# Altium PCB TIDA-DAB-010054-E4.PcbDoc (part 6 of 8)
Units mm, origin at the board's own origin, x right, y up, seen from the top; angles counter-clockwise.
Board outline 300 x 180 mm, 4 copper layers (Top Layer, Inner Layer1, Inner Layer2, Bottom Layer), stack 1.605 mm thick; 873 components, 388 nets, 2405 pads, 1542 vias.
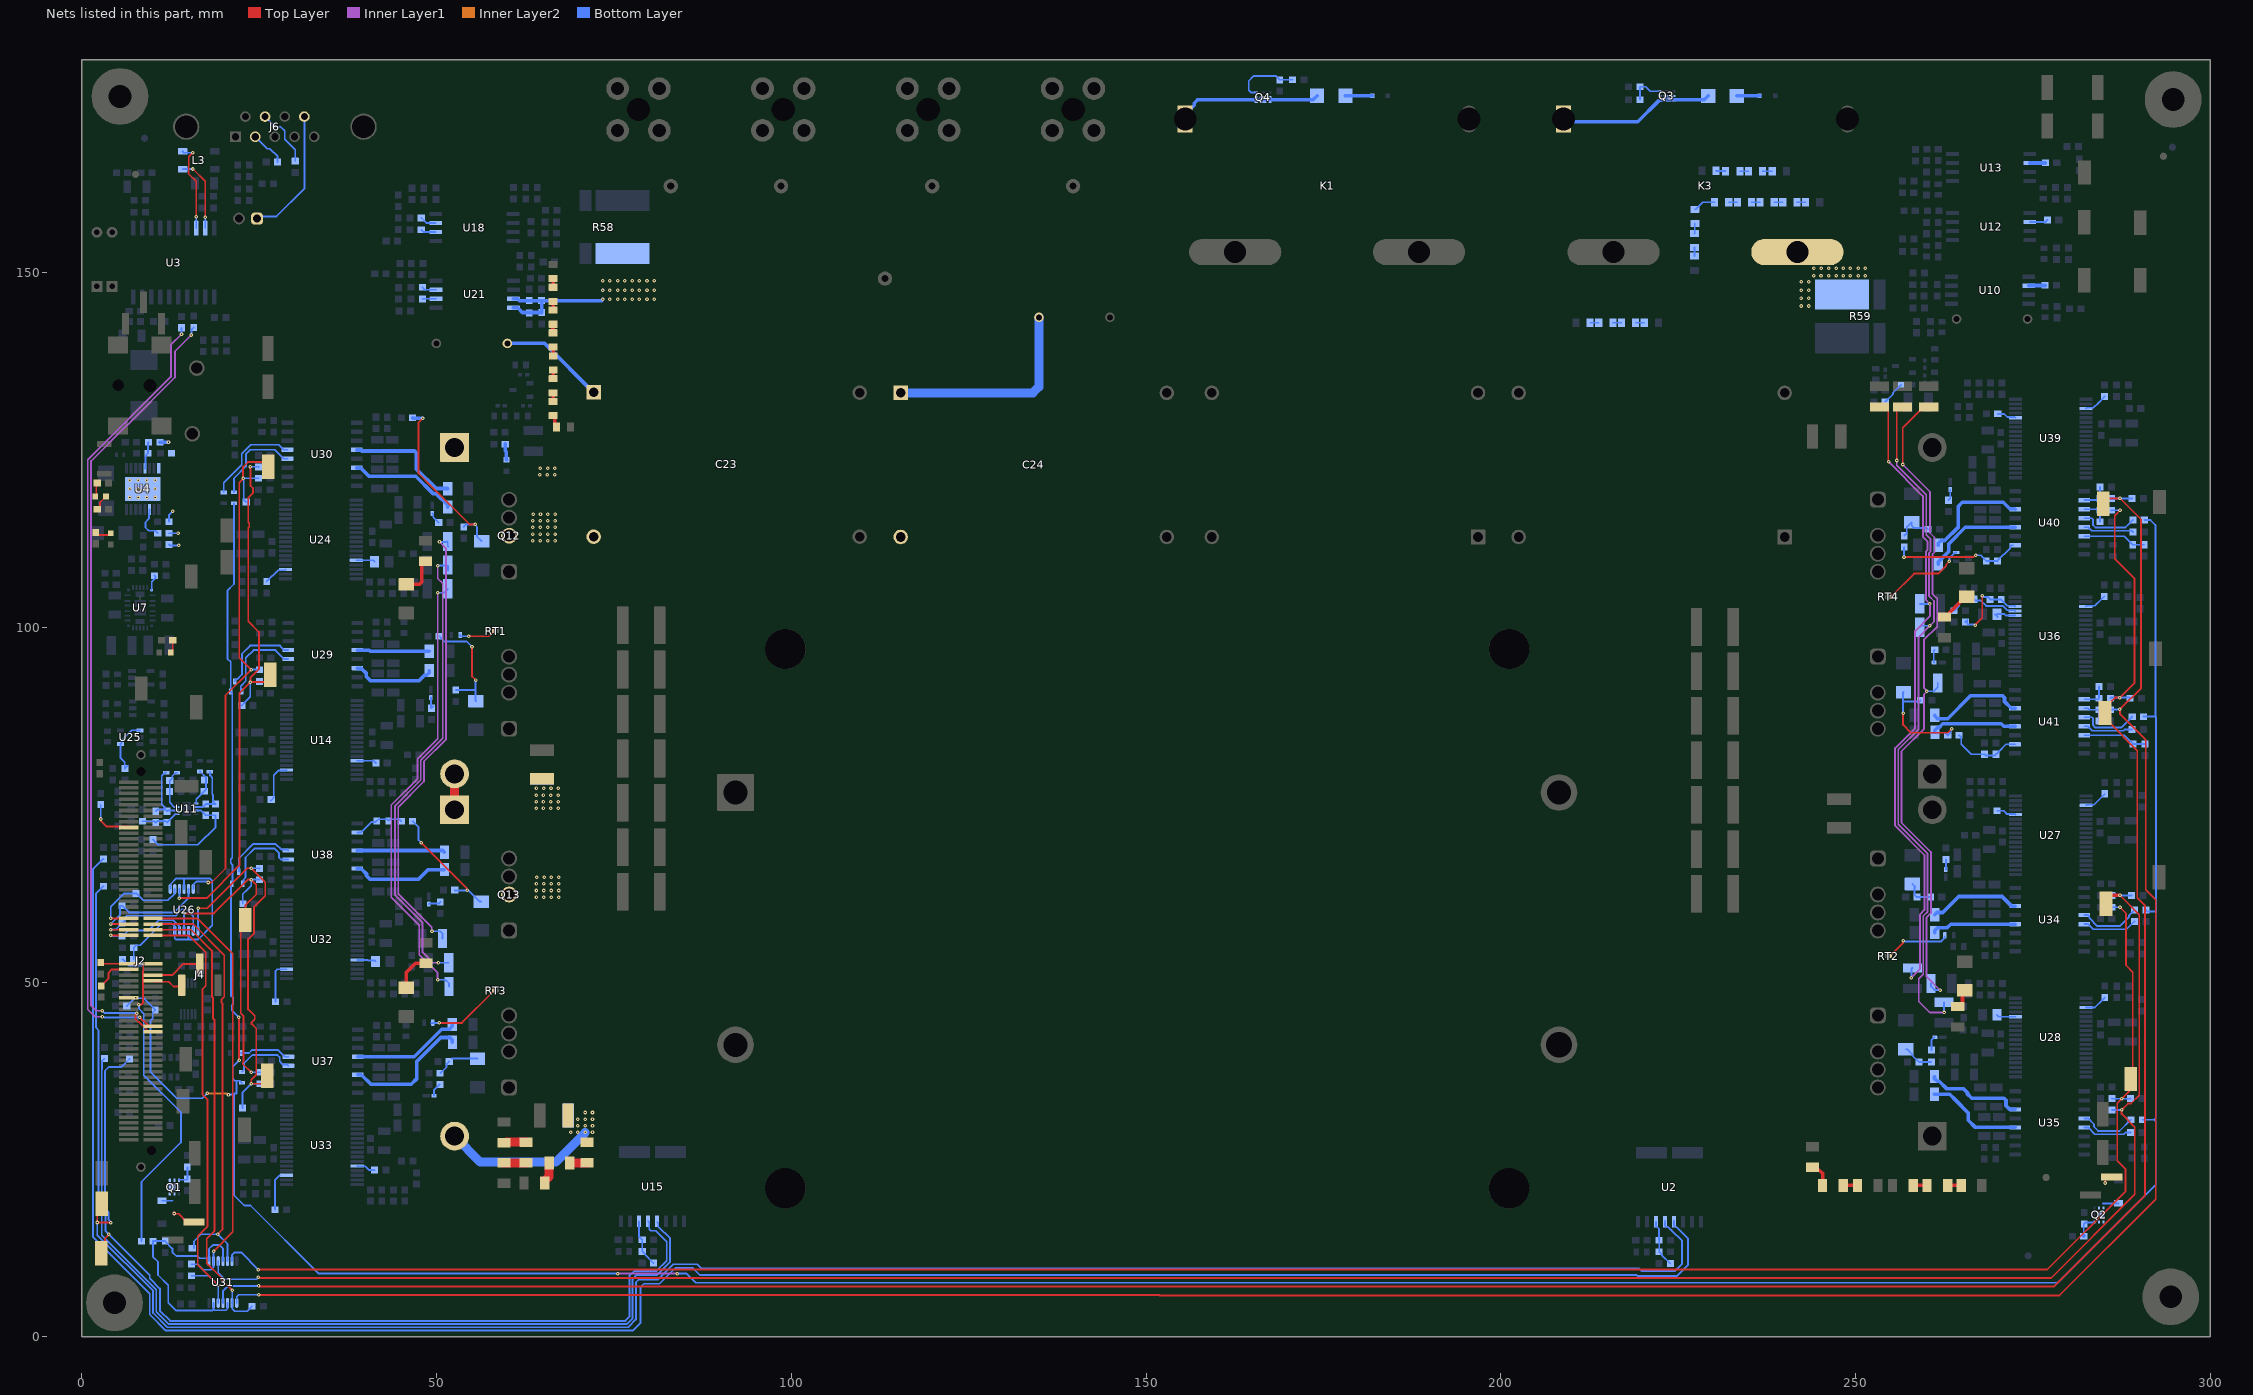
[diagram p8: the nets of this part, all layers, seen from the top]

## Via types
v1: diameter 0.5, hole 0.2, Top Layer to Bottom Layer, tented both sides, 1530 vias
v2: diameter 0.5, hole 0.2, Top Layer to Bottom Layer, 12 vias

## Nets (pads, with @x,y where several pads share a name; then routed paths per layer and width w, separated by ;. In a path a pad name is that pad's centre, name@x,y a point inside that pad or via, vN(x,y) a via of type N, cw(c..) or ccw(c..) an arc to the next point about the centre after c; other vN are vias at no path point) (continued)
NetC283_1: C283.1 R346.1 R350.2 U36.34 | length 12
  Top Layer w0.254: v1(266.849,100.307) 266.849,100.359 267.847,101.358 267.847,104.433 v1(267.818,104.462)
  Bottom Layer w0.254: R346.1@265.467,100.755 265.724,101.012 265.724,100.523 265.84,100.407 266.682,100.407 266.782,100.307 v1(266.849,100.307) ; v1(267.818,104.462) 267.914,104.462 268.105,104.271 268.599,104.271 268.947,103.923 R350.2@268.947,103.898 C283.1@270.522,103.898 270.522,103.873 271.363,103.033 272.381,103.033 U36.34@272.476,102.938
NetC284_1: C284.1 R347.1 R351.2 U36.33 | length 10.3
  Bottom Layer w0.254: R347.1@263.867,102.34 263.892,102.34 264.588,103.037 264.588,103.313 264.782,103.507 264.782,103.602 265.327,104.147 266.53,104.147 266.903,103.774 267.629,103.774 268.39,103.013 270.71,103.013 271.339,102.383 272.381,102.383 U36.33@272.476,102.288
NetC293_1: C293.1 R352.2 U40.10 | length 3.9
  Bottom Layer w0.254: U40.10@282.225,117.911 284.218,117.911 R352.2@284.436,118.129 C293.1@284.436,119.763
NetC299_1: C299.1 R353.2 U41.10 | length 3.8
  Bottom Layer w0.254: U41.10@282.205,89.851 284.14,89.851 R353.2@284.289,89.999 C299.1@284.289,91.65
NetC302_1: C302.1 R322.1 R326.2 U38.2 | length 7.3
  Bottom Layer w0.254: U38.2@38.866,71.087 39.391,71.087 40.871,72.567 41.471,72.567 41.844,72.94 43.086,72.94 R326.2@43.304,72.723 43.521,72.94 44.759,72.94 R322.1@45.052,72.648
NetC303_1: C303.1 R354.2 U40.11 | length 3.9
  Bottom Layer w0.254: U40.11@282.225,116.641 284.244,116.641 R354.2@284.416,116.469 284.436,116.449 C303.1@284.436,114.861
NetC304_1: C304.1 R355.2 U41.11 | length 3.8
  Bottom Layer w0.254: U41.11@282.205,88.581 282.73,88.581 282.929,88.382 R355.2@284.289,88.382 C304.1@284.289,86.793
NetC305_1: C305.1 R375.2 U40.14 | length 8.9
  Bottom Layer w0.254: U40.14@282.225,112.831 287.857,112.831 289.036,111.653 C305.1@289.036,111.628 R375.2@290.625,111.628
NetC308_1: C308.1 R372.1 R377.2 U40.2 | length 18.4
  Top Layer w0.254: v1(256.816,109.852) 256.846,109.882 266.559,109.882 266.832,110.154 v1(266.898,110.154)
  Bottom Layer w0.254: v1(256.816,109.852) 256.816,111.253 R372.1@256.862,111.299 ; v1(266.898,110.154) 267.608,110.154 268.057,109.706 268.057,109.681 R377.2@268.405,109.333 C308.1@269.976,109.333 269.976,109.358 271.777,111.159 271.777,111.388 271.95,111.561 U40.2@272.2,111.561
NetC309_1: C309.1 R376.2 U41.14 | length 9.1
  Bottom Layer w0.254: U41.14@282.205,84.771 287.861,84.771 288.724,83.908 288.749,83.908 289.097,83.56 C309.1@289.097,83.535 R376.2@290.786,83.535
NetC312_1: C312.1 R374.1 R378.2 U41.2 | length 10.3
  Bottom Layer w0.254: R374.1@264.586,84.766 264.869,84.483 264.869,83.516 266.281,82.104 R378.2@268.164,82.104 268.32,81.948 269.636,81.948 C312.1@269.791,82.104 269.791,82.129 270.139,82.477 270.164,82.477 271.189,83.501 U41.2@272.455,83.501
NetC315_1: C315.1 R135.1 R138.1 U11.2 | length 8.9
  Bottom Layer w0.254: R135.1@10.457,74.075 10.687,74.305 11.708,74.305 11.708,74.668 11.698,74.678 11.673,74.678 11.313,75.039 11.313,79.088 11.744,79.519 R138.1@11.944,79.519 ; C315.1@11.826,74.305 C315.1@12.056,74.075 12.14,74.159 U11.2@13.455,74.159
NetC315_2: C315.2 R135.2 R139.1 U11.1 | length 5.8
  Bottom Layer w0.254: R139.1@8.601,72.66 10.272,72.66 R135.2@10.457,72.475 10.684,72.702 11.829,72.702 C315.2@12.056,72.475 12.056,72.5 12.404,72.848 12.423,72.848 U11.1@13.234,73.659 ; U11.1@13.234,73.659 U11.1@13.455,73.659 U11.1@13.234,73.659
NetC316_1: C316.1 R142.1 R143.2 U11.3 | length 6
  Bottom Layer w0.254: U11.3@13.455,74.659 13.453,74.661 13.084,74.661 12.43,75.315 12.43,78.392 R143.2@12.427,78.395 12.442,78.395 12.79,78.743 12.79,79.038 13.255,79.502 R142.1@13.455,79.502
NetC317_1: C317.1 R153.1 R156.1 U11.6 | length 7.8
  Bottom Layer w0.254: U11.6@16.155,74.659 16.954,74.659 17.028,74.732 17.145,74.732 17.493,75.08 C317.1@17.493,75.105 17.493,75.097 R153.1@18.886,75.097 18.538,75.445 18.538,76.33 18.427,76.441 18.427,78.81 18.12,79.117 18.12,79.517 18.088,79.548 R156.1@18.088,79.64
NetC317_2: C317.2 R153.2 R157.1 U11.7 | length 14.9
  Bottom Layer w0.254: R157.1@10.06,70.077 10.085,70.077 10.822,69.34 16.406,69.34 18.886,71.82 R153.2@18.886,73.497 17.493,73.497 17.493,73.53 16.866,74.157 16.157,74.157 U11.7@16.155,74.159
NetC318_1: C318.1 R159.1 R160.2 U11.5 | length 5.4
  Bottom Layer w0.254: U11.5@16.155,75.159 16.155,75.781 17.265,76.89 R160.2@17.29,76.89 17.52,77.12 17.52,78.841 R159.1@16.69,79.67
NetC333_1: C333.1 R37.2 R40.1 U2.8 | length 6.7
  Bottom Layer w0.254: U2.8@221.855,16.205 221.855,15.68 222.288,15.247 C333.1@222.288,13.614 222.314,13.589 R40.1@222.314,11.989 222.339,11.989 222.687,11.641 222.687,11.514 223.863,10.338 R37.2@223.888,10.338
NetC334_1: C334.1 R45.2 R46.1 U15.8 | length 6.8
  Bottom Layer w0.254: U15.8@78.562,16.309 78.562,14.123 79.007,13.678 R46.1@79.007,12.04 79.032,12.04 79.38,11.692 79.38,11.616 80.582,10.414 R45.2@80.607,10.414
NetD1_2: D1.2 D2.2 | length 3.8
  Bottom Layer w0.508: D2.2@178.118,174.904 D1.2@181.884,174.904
NetD3_2: D3.2 D4.2 | length 3.2
  Bottom Layer w0.508: D4.2@233.24,174.88 D3.2@236.46,174.88
NetD6_1: D6.1 R68.1 | length 2
  Top Layer w0.254: D6.1@1.948,118.425 2.085,118.562 2.085,120.185 R68.1@2.216,120.316
NetD6_2: D6.2 R70.2 | length 2.3
  Top Layer w0.254: R70.2@2.216,116.631 2.241,116.631 2.589,116.979 2.589,117.576 3.302,118.289 3.312,118.289 D6.2@3.448,118.425
NetD8_1: D8.1 R76.2 | length 2.4
  Top Layer w0.254: R76.2@2,113.37 2,113.345 2.358,112.987 3.865,112.987 D8.1@4.134,113.256
NetD10_1: D10.1 R81.2 | length 1.9
  Top Layer w0.254: D10.1@12.558,96.435 12.831,96.708 12.831,96.83 12.858,96.857 R81.2@12.858,98.161
NetD11_1: D11.1 R13.1 | length 3.4
  Bottom Layer w0.254: R13.1@254.166,131.773 254.191,131.773 255.27,132.852 255.27,133.054 D11.1@256.4,134.184
NetD12_1: D12.1 R14.1 | length 2.3
  Bottom Layer w0.508: R14.1@59.691,125.832 59.691,124.904 59.84,124.756 59.84,123.646 D12.1@59.891,123.594
NetD13_2: D13.2 J1.2 Q1.1 Q1.2 Q1.5 Q1.6 Q1.8 | length 4.8
  Top Layer w0.254: v1(13.083,17.387) 13.13,17.34 13.69,17.34 14.85,16.18 J1.2@15.85,16.18
  Top Layer w0.508: v1@13.057,17.361 v1(13.083,17.387)
  Bottom Layer w0.254: D13.2@11.333,19.196 12.804,19.196
NetD14_2: D14.2 R208.1 R217.2 | length 15.9
  Top Layer w0.254: v1(55.022,97.225) 55.022,93.073 v1(55.532,92.563)
  Bottom Layer w0.254: R217.2@50.413,98.725 50.438,98.725 50.786,98.377 50.786,98.352 51.144,97.993 54.254,97.993 v1(55.022,97.225) ; R208.1@52.729,91.15 55.532,91.15 ; v1(55.532,92.563) 55.532,91.15 ; D14.2@55.569,89.593 55.532,89.63 55.532,91.15
NetD15_2: D15.2 R154.1 R155.2 | length 25
  Top Layer w0.254: v1(48.099,129.474) 47.498,128.872 47.498,121.662 49.283,119.877 54.675,114.485 v1(55.468,114.485)
  Bottom Layer w0.254: R154.1@53.858,114.135 53.858,114.137 54.206,114.485 v1(55.468,114.485) 55.468,114.419 55.725,114.162 55.725,112.766 D15.2@56.381,112.11
  Bottom Layer w0.508: R155.2@46.661,129.512 46.7,129.474 v1(48.099,129.474)
NetD16_2: D16.2 J3.2 Q2.1 Q2.2 Q2.5 Q2.6 Q2.8 | length 3.8
  Top Layer w0.254: v1@285.155,21.657 v1(285.183,21.685) 285.183,22.182 285.556,22.555 J3.2@286.082,22.555
  Bottom Layer w0.254: 284.812,18.808 D16.2@287.032,18.808
NetD17_2: D17.2 R24.1 | length 1.7
  Bottom Layer w0.254: D17.2@49.443,116.062 49.566,115.939 49.566,115.492 50.311,114.747 R24.1@50.336,114.747
NetD18_2: D18.2 R267.1 R276.2 | length 4.1
  Bottom Layer w0.254: D18.2@257.991,63.825 258.399,63.418 258.29,63.309 258.29,62.323 258.638,61.975 R276.2@258.663,61.975 R267.1@260.54,61.975
NetD19_2: D19.2 R273.1 R278.2 | length 4.4
  Bottom Layer w0.254: D19.2@257.063,40.545 257.253,40.545 258.016,39.782 258.016,39.619 258.888,38.748 R278.2@258.913,38.748 R273.1@260.668,38.748
NetD20_2: D20.2 R25.1 | length 1.8
  Bottom Layer w0.254: D20.2@49.24,90.082 49.24,88.647 R25.1@49.301,88.586 ; R25.1@49.404,88.793 49.458,88.74 R25.1@49.578,88.86
NetD21_2: D21.2 R26.1 | length 1.4
  Bottom Layer w0.254: D21.2@262.716,65.874 R26.1@262.716,67.297
NetD22_2: D22.2 R317.1 R322.2 | length 17.3
  Top Layer w0.254: v1(47.889,69.628) 54.291,63.226 54.291,62.969 v1(54.338,62.921)
  Bottom Layer w0.254: R322.2@46.652,72.648 46.677,72.648 47.5,71.825 47.5,70.017 v1(47.889,69.628) ; R317.1@52.591,62.972 52.642,62.921 v1(54.338,62.921) 54.385,62.874 54.591,62.874 56.13,61.335 D22.2@56.32,61.335
NetD23_2: D23.2 R27.1 | length 2
  Bottom Layer w0.254: R27.1@260.704,40.415 260.704,41.868 261.053,42.217 D23.2@261.153,42.217
NetD24_2: D24.2 R6.2 | length 5.5
  Top Layer w0.508: D24.2@45.778,106.049 47.62,106.049 47.917,106.347 47.917,108.901 48.313,109.297 R6.2@48.467,109.297
NetD25_2: D25.2 R362.1 R372.2 | length 5.5
  Bottom Layer w0.254: R372.2@256.862,112.899 257.21,113.247 257.21,114.065 257.719,114.574 D25.2@257.917,114.773 257.917,114.318 258.255,113.98 R362.1@260.031,113.98 ; R362.1@260.031,113.98 R362.1@260.2,113.811 R362.1@260.031,113.98
NetD26_2: D26.2 R311.1 R320.2 | length 5.8
  Bottom Layer w0.254: R311.1@50.539,37.155 50.564,37.155 51.443,38.034 51.443,38.455 51.791,38.803 R320.2@51.816,38.803 ; R320.2@52.196,39.213 D26.2@55.798,39.213
NetD27_2: D27.2 R369.1 R374.2 | length 16.4
  Top Layer w0.254: v1(256.687,87.852) 256.687,86.231 257.774,85.144 263.009,85.144 v1(263.553,85.688)
  Bottom Layer w0.254: v1(256.687,87.852) 256.687,89.541 ; D27.2@256.745,90.855 256.687,90.797 256.687,89.541 ; R369.1@259.181,89.708 259.013,89.541 256.687,89.541 ; R374.2@262.638,85.114 R374.2@262.986,84.766 263.011,84.766 263.359,85.114 263.359,85.398 263.553,85.591 v1(263.553,85.688)
NetD28_2: D28.2 R7.2 | length 2.8
  Top Layer w0.508: R7.2@264.386,46.57 264.661,46.57 265.057,46.966 265.057,48.526 D28.2@265.367,48.835
NetD29_2: D29.2 R20.2 | length 5.5
  Top Layer w0.508: D29.2@45.773,49.197 45.773,51.348 47.071,52.646 R20.2@48.534,52.646
NetD30_2: D30.2 R21.2 | length 4.4
  Top Layer w0.508: R21.2@262.512,101.432 262.787,101.432 263.183,101.828 263.183,102.012 265.447,104.275 D30.2@265.637,104.275
NetD31_2: D31.2 R31.1 | length 1.7
  Bottom Layer w0.254: D31.2@48.957,60.988 49.029,61.059 50.35,61.059 R31.1@50.564,61.273
NetD32_2: D32.2 R32.1 | length 1.9
  Bottom Layer w0.254: D32.2@49.684,33.993 49.684,34.808 50.459,35.583 R32.1@50.484,35.583
NetD33_2: D33.2 R34.1 | length 1.9
  Bottom Layer w0.254: D33.2@261.058,95.031 261,95.09 261,96.697 R34.1@261.145,96.842
NetD34_2: D34.2 R35.1 | length 1.6
  Bottom Layer w0.254: R35.1@263.078,117.897 263.332,118.151 D34.2@263.332,119.418
NetJ2_17: J2.17 R3.2 | length 6.6
  Top Layer w0.254: v1(2.714,72.982) 2.761,72.934 2.761,72.668 3.144,72.285 3.527,71.902 6.546,71.902 J2.17@6.669,71.779
  Bottom Layer w0.254: v1(2.714,72.982) R3.2@2.714,74.996
NetJ2_57: J2.57 R10.2 | length 4
  Top Layer w0.254: R10.2@2.718,52.759 2.898,52.579 J2.57@6.669,52.579
NetJ2_59: J2.59 R19.2 | length 5.3
  Top Layer w0.254: R19.2@2.766,49.469 2.766,49.494 3.114,49.842 3.139,49.842 3.81,50.513 3.81,51.308 4.281,51.779 J2.59@6.669,51.779
NetJ2_80: J2.80 R38.1 | length 111.7
  Top Layer w0.254: v1(8.183,45.014) 8.652,44.545 8.786,44.545 9.429,43.902 9.946,43.902 J2.80@10.069,43.779
  Inner Layer1 w0.254: v1(2.949,45.104) 1.917,45.104 0.889,46.132 0.889,123.622 6.134,128.867 6.176,128.867 12.59,135.281 12.59,139.823 v1(14.085,141.317)
  Bottom Layer w0.254: v1(2.949,45.104) 2.996,45.057 3.17,45.057 3.213,45.014 v1(8.183,45.014) ; v1(14.085,141.317) R38.1@14.085,142.211
NetJ2_82: J2.82 R41.1 | length 112.6
  Top Layer w0.254: v1(7.778,45.626) 7.778,45.559 7.603,45.384 7.603,44.773 7.955,44.422 8.043,44.422 9.363,43.102 9.946,43.102 J2.82@10.069,42.979
  Inner Layer1 w0.254: v1(2.924,45.952) 2.074,45.952 1.346,46.68 1.346,123.433 6.323,128.41 6.366,128.41 13.166,135.21 13.166,138.888 v1(15.459,141.181)
  Bottom Layer w0.254: v1(2.924,45.952) 3.251,45.626 v1(7.778,45.626) ; v1(15.459,141.181) 15.481,141.203 15.481,141.895 R41.1@15.826,142.24
NetJ6_2: J6.2 R56.2 | length 5.1
  Bottom Layer w0.254: J6.2@24.475,169.12 26.158,167.437 26.543,167.437 27.63,166.35 R56.2@27.63,165.547
NetJ6_7: J6.7 R53.2 | length 8.5
  Bottom Layer w0.254: J6.7@25.86,171.96 27.28,170.54 28.038,170.54 28.63,169.947 28.63,168.752 30.112,167.27 R53.2@30.112,165.677
NetJ6_9: J6.9 J10.1 | length 18.6
  Bottom Layer w0.254: J10.1@24.728,157.596 25.013,157.881 27.467,157.881 31.4,161.814 J6.9@31.4,171.96
NetK3_4: K3.4 R59.4
  other v1: 242.333,145.272 243.38,145.272 242.305,146.342 243.38,146.342 242.333,147.472 243.38,147.472 242.338,148.672 243.38,148.672 244.119,149.528 245.119,149.528 246.219,149.528 247.239,149.528 248.251,149.528 249.251,149.528 250.351,149.528 251.371,149.528 244.128,150.56 245.128,150.56 246.228,150.56 247.248,150.56 248.26,150.56 249.26,150.56 250.36,150.56 251.38,150.56
NetL3_1: L3.1 U3.19 | length 10.5
  Top Layer w0.254: v1(15.701,164.572) 17.435,162.839 v1(17.435,157.748)
  Bottom Layer w0.254: L3.1@14.245,164.55 14.267,164.572 v1(15.701,164.572) ; U3.19@17.435,156.24 v1(17.435,157.748)
NetL3_2: L3.2 U3.18 | length 12.8
  Top Layer w0.254: v1(15.673,166.867) 15.121,166.315 15.121,163.874 16.165,162.83 v1(16.165,157.852)
  Bottom Layer w0.254: L3.2@14.245,167.05 14.428,166.867 v1(15.673,166.867) ; U3.18@16.165,156.24 v1(16.165,157.852)
NetQ1_3: Q1.3 R1.2 R2.2 | length 2.9
  Bottom Layer w0.254: Q1.3@13.733,22.146 14.813,22.146 R2.2@14.913,22.245 R1.2@14.913,23.91
NetQ2_3: Q2.3 R4.2 R5.2 | length 3.4
  Bottom Layer w0.254: R4.2@282.14,14.2 282.14,15.845 282.425,16.129 283.622,16.129 283.645,16.152 Q2.3@283.645,16.204
  Bottom Layer w0.508: R4.2@282.14,14.2 R4.2@282.182,14.242
NetQ3_3: Q3.3 R48.2 R51.2 | length 4.8
  Bottom Layer w0.254: R51.2@219.6,174.32 R48.2@219.6,176.16 220.436,176.16 221.066,175.53 Q3.3@222.299,175.53
NetQ4_3: Q4.3 R39.2 R43.2 | length 9.2
  Bottom Layer w0.254: Q4.3@165.535,175.336 164.804,175.336 164.48,175.66 164.48,176.979 165.201,177.7 168.3,177.7 168.487,177.513 168.512,177.513 168.86,177.165 R43.2@168.86,177.14 R39.2@170.64,177.14
NetR8_1: R8.1 U24.32 | length 2.7
  Bottom Layer w0.254: U24.32@38.715,109.435 41.108,109.435 R8.1@41.303,109.24
NetR9_1: R9.1 U28.32 | length 2.7
  Bottom Layer w0.254: R9.1@269.909,45.372 270.161,45.12 U28.32@272.525,45.12
NetR11_1: R11.1 U32.32 | length 2.7
  Bottom Layer w0.254: U32.32@38.855,53.115 40.299,53.115 40.36,53.054 41.294,53.054 R11.1@41.448,52.9
NetR12_1: R12.1 U36.32 | length 3.1
  Bottom Layer w0.254: R12.1@269.649,101.807 R12.1@269.997,101.459 ; R12.1@269.932,101.807 269.984,101.859 270.965,101.859 271.17,101.654 272.459,101.654 U36.32@272.476,101.638
NetR16_2: R16.2 RT1.2 | length 5.2
  Top Layer w0.254: v1(54.544,98.725) 57.417,98.725 58.025,99.332 RT1.2@58.025,99.457
  Bottom Layer w0.254: R16.2@53.346,98.901 53.346,98.835 53.457,98.725 v1(54.544,98.725)
NetR17_2: R17.2 RT2.2 | length 9.2
  Top Layer w0.254: RT2.2@254.955,53.668 254.955,53.793 256.658,55.496 256.658,55.758 v1(256.705,55.805)
  Bottom Layer w0.254: v1(256.705,55.805) 256.785,55.725 262.054,55.725 262.568,56.239 R17.2@262.568,56.452
NetR18_2: R18.2 RT3.2 | length 10.7
  Top Layer w0.254: v1(50.425,44.246) 53.598,44.246 57.977,48.624 57.977,48.749 RT3.2@58.025,48.797
  Bottom Layer w0.254: 49.252,44.27 49.276,44.246 v1(50.425,44.246)
NetR29_2: R29.2 RT4.2 | length 12.3
  Top Layer w0.254: RT4.2@254.955,104.283 254.955,104.408 255.003,104.456 255.128,104.456 258.233,107.561 261.663,107.561 262.761,108.659 262.761,108.839 263.191,109.268 v1(263.191,109.301)
  Bottom Layer w0.254: v1(263.191,109.301) 263.238,109.348 263.238,109.809 263.954,110.525 R29.2@264.167,110.525
NetR61_1: R61.1 U21.7 | length 2
  Bottom Layer w0.254: R61.1@48.046,147.897 48.391,147.552 U21.7@49.953,147.552
NetR63_1: R63.1 U21.6 | length 1.9
  Bottom Layer w0.254: R63.1@48.024,146.255 48.051,146.282 U21.6@49.953,146.282
NetR64_1: R64.1 R95.1 | length 1.4
  Bottom Layer w0.254: R95.1@236.893,164.256 R64.1@238.251,164.256
NetR66_1: R66.1 R128.2 | length 3.1
  Top Layer w1.27: R66.1@59.525,27.37 59.8,27.37 59.86,27.43 R128.2@62.64,27.43
NetR73_1: R73.1 U4.11 | length 4.8
  Bottom Layer w0.254: U4.11@9.582,116.587 9.582,116.059 9.487,115.964 9.487,115.277 9.017,114.807 9.017,114.06 9.489,113.589 10.385,113.589 R73.1@10.733,113.24
NetR84_2: R84.2 U7.1 | length 2.3
  Bottom Layer w0.254: U7.1@9.883,105.243 9.883,106.402 10.408,106.927 10.408,107.143 R84.2@10.276,107.275
NetR85_2: R85.2 U29.12 | length 12.1
  Bottom Layer w0.254: R85.2@22.6,90.935 22.439,91.096 22.439,91.714 23.151,92.425 23.151,95.688 24.243,96.78 27.321,96.78 28.591,95.51 U29.12@29.116,95.51
NetR92_1: R92.1 U10.6 | length 2.3
  Bottom Layer w0.508: U10.6@274.39,148.135 274.413,148.158 276.677,148.158 R92.1@276.7,148.181
NetR95_2: R95.2 R97.1 | length 1.2
  Bottom Layer w0.254: R97.1@233.687,164.256 R95.2@234.893,164.256
NetR96_1: R96.1 R98.1 | length 1.2
  Bottom Layer w0.254: R96.1@227.3,152.298 R98.1@227.3,153.504
NetR97_2: R97.2 R100.2 | length 1.4
  Bottom Layer w0.254: R100.2@230.33,164.336 230.37,164.296 231.647,164.296 R97.2@231.687,164.256
NetR98_2: R98.2 R102.1 | length 1.4
  Bottom Layer w0.254: R98.2@227.3,155.504 227.34,155.544 R102.1@227.34,156.891
NetR101_1: R101.1 R103.2 | length 1.2
  Bottom Layer w0.254: R101.1@212.594,142.912 R103.2@213.799,142.912
NetR102_2: R102.2 R105.2 | length 3.2
  Bottom Layer w0.254: R102.2@227.34,158.891 227.465,158.891 228.462,159.888 R105.2@230.119,159.888
NetR103_1: R103.1 R107.1 | length 1.2
  Bottom Layer w0.254: R103.1@215.799,142.912 R107.1@217.004,142.912
NetR105_1: R105.1 R106.2 | length 1.2
  Bottom Layer w0.254: R105.1@232.119,159.888 R106.2@233.324,159.888
NetR106_1: R106.1 R108.2 | length 1.2
  Bottom Layer w0.254: R106.1@235.324,159.888 R108.2@236.529,159.888
NetR107_2: R107.2 R109.2 | length 1.2
  Bottom Layer w0.254: R107.2@219.004,142.912 R109.2@220.209,142.912
NetR108_1: R108.1 R110.1 | length 1.2
  Bottom Layer w0.254: R108.1@238.529,159.888 R110.1@239.734,159.888
NetR110_2: R110.2 R111.2 | length 1.2
  Bottom Layer w0.254: R110.2@241.734,159.888 R111.2@242.939,159.888
NetR112_2: R112.2 R124.2 | length 1.8
  Top Layer w0.508: R124.2@66.455,129.817 66.685,129.587 66.685,128.467 R112.2@66.915,128.237
NetR116_1: R116.1 U12.6 | length 2.6
  Bottom Layer w0.254: U12.6@274.543,157.097 276.717,157.097 R116.1@277.02,157.4
NetR117_1: R117.1 U13.6 | length 2.2
  Bottom Layer w0.508: U13.6@274.55,165.415 274.562,165.427 276.728,165.427 R117.1@276.74,165.44
NetR124_1: R124.1 R145.2 | length 1.2
  Top Layer w0.508: R124.1@66.455,131.817 R124.1@66.455,131.817 66.457,133.028 R145.2@66.458,133.03
NetR125_1: R125.1 TP16.1 U2.7 | length 277.8
  Top Layer w0.254: TP16.1@2.851,18.777 2.222,18.148 v1(2.222,16.12) 2.226,16.116 4.132,16.116 v1(4.136,16.112)
  Bottom Layer w0.254: v1(2.222,16.12) 2.222,14.332 10.079,6.475 10.079,3.364 12.097,1.346 77.011,1.346 78.124,2.458 78.124,7.669 78.553,8.098 81.239,8.098 83.376,10.235 86.767,10.235 87.352,9.651 219.432,9.651 219.786,9.296 224.561,9.296 225.552,10.287 225.552,13.538 224.04,15.05 223.988,15.05 223.531,15.507 223.298,15.507 223.125,15.68 U2.7@223.125,16.33 ; v1(4.136,16.112) 4.136,16.178 3.818,16.496 3.818,17.541 3.308,18.051 3.308,37.49 3.867,38.049 5.651,38.049 6.756,39.155 R125.1@6.756,39.18
NetR126_1: R126.1 U2.6 | length 300.7
  Bottom Layer w0.254: R126.1@3.075,67.35 3.05,67.35 1.6,65.901 1.6,14.108 9.622,6.087 9.622,3.159 11.892,0.889 77.685,0.889 78.746,1.95 78.746,6.958 79.263,7.475 81.439,7.475 83.673,9.709 86.151,9.709 87.147,8.712 219.126,8.712 219.278,8.56 224.8,8.56 226.39,10.15 226.39,13.818 224.701,15.507 224.568,15.507 224.395,15.68 U2.6@224.395,16.33
NetR127_1: R127.1 R222.2 | length 3.5
  Top Layer w0.508: R127.1@243.9,23.896 244.296,23.5 244.876,23.5 245.344,23.032 R222.2@245.344,21.345
NetR128_1: R128.1 R226.2 | length 3.1
  Top Layer w1.27: R226.2@59.525,24.535 59.527,24.532 62.638,24.532 R128.1@62.64,24.53
NetR137_1: R137.1 U18.7 | length 2.3
  Bottom Layer w0.254: R137.1@47.877,157.671 47.902,157.671 48.618,156.955 U18.7@49.91,156.955
NetR141_1: R141.1 U18.6 | length 2.2
  Bottom Layer w0.254: R141.1@47.877,156.019 48.211,155.685 U18.6@49.91,155.685
NetR144_2: R144.2 U30.12 | length 12.6
  Bottom Layer w0.254: R144.2@21.48,119.06 21.48,120.981 23.165,122.666 23.165,124.376 23.8,125.011 27.229,125.011 28.49,123.751 U30.12@29.015,123.751
NetR145_1: R145.1 R146.2 | length 1.2
  Top Layer w0.508: R145.1@66.458,135.03 66.467,135.038 66.467,136.239 R146.2@66.476,136.247
NetR146_1: R146.1 R148.1 | length 1.3
  Top Layer w0.508: R148.1@66.441,139.497 66.458,139.48 66.458,138.264 R146.1@66.476,138.247
NetR147_2: R147.2 U29.13 | length 11.7
  Bottom Layer w0.254: R147.2@21.601,92.351 21.601,92.542 21.728,92.669 21.919,92.669 22.61,93.36 22.61,96.275 23.746,97.411 27.96,97.411 28.591,96.78 U29.13@29.116,96.78
NetR148_2: R148.2 R149.2 | length 1.2
  Top Layer w0.508: R148.2@66.441,141.497 R149.2@66.442,142.698
NetR149_1: R149.1 R151.2 | length 1.2
  Top Layer w0.508: R149.1@66.442,144.698 66.449,144.705 66.449,145.91 R151.2@66.455,145.917
NetR150_2: R150.2 U30.13 | length 13.7
  Bottom Layer w0.254: R150.2@20.051,119.02 20.051,120.37 22.565,122.885 22.565,124.424 23.856,125.714 27.797,125.714 28.49,125.021 U30.13@29.015,125.021
NetR151_1: R151.1 R152.2 | length 1.2
  Top Layer w0.508: R151.1@66.455,147.917 R152.2@66.455,149.137
NetR166_1: R166.1 U25.1 U25.4 | length 8
  Bottom Layer w0.254: R166.1@6.455,80.452 6.107,80.104 R166.1@6.107,80.079 6.101,80.086 6.101,80.984 5.475,81.61 U25.4@5.475,83.548 5.502,83.548 5.675,83.721 5.675,84.085 7.064,85.474 7.998,85.474 8.025,85.448 U25.1@8.225,85.448
NetR167_1: R167.1 TP18.1 U15.7 | length 128.1
  Top Layer w0.254: TP18.1@2.781,11.802 3.302,12.324 3.302,13.892 3.82,14.41 v1(3.82,14.477)
  Bottom Layer w0.254: R167.1@3.226,39.205 2.878,38.857 2.878,37.706 2.851,37.68 2.851,17.862 3.361,17.352 3.361,14.936 v1(3.82,14.477) 9.611,8.685 9.611,8.236 11.039,6.808 11.039,3.698 12.476,2.261 76.633,2.261 77.2,2.828 77.2,8.589 77.916,9.305 81.023,9.305 82.474,10.756 82.474,13.411 80.924,14.961 80.213,14.961 80.005,15.169 80.005,16.136 U15.7@79.832,16.309
NetR168_1: R168.1 U15.6 | length 150.2
  Bottom Layer w0.254: R168.1@3.08,63.492 3.055,63.492 2.057,62.495 2.057,43.553 2.394,43.217 2.394,17.672 2.858,17.208 2.858,14.342 10.536,6.664 10.536,3.553 12.287,1.803 76.822,1.803 77.657,2.638 77.657,8.141 78.256,8.74 81.105,8.74 82.931,10.566 82.931,13.894 81.275,15.55 81.275,16.03 U15.6@81.135,16.17
NetR173_2: R173.2 R178.2 U26.1 U26.4 U26.10 U26.13 | length 32.9
  Bottom Layer w0.254: R173.2@7.363,53.22 R178.2@7.363,54.848 7.711,55.196 8.264,55.196 11.32,58.251 12.723,58.251 13.106,57.869 13.106,57.258 U26.13@13.143,57.221 13.143,56.143 13.292,55.994 15.074,55.994 15.093,56.013 U26.10@15.093,57.221 ; U26.1@12.493,63.121 12.531,63.158 12.531,63.769 13.372,64.611 18.088,64.611 18.428,64.271 18.428,57.996 16.427,55.994 15.093,55.994 ; U26.4@14.443,63.121 14.443,64.591 14.46,64.608
NetR183_1: R183.1 U14.32 | length 3.2
  Bottom Layer w0.254: U14.32@38.816,81.181 39.241,81.181 R183.1@41.171,81.181 ; R183.1@41.171,81.181 41.486,80.865 R183.1@41.171,81.181
NetR185_2: R185.2 U14.3 | length 5.8
  Bottom Layer w0.254: R185.2@26.683,75.59 26.708,75.59 27.056,75.938 27.056,75.963 27.087,75.995 27.087,79.157 27.762,79.832 28.817,79.832 U14.3@28.866,79.881
NetR187_2: R187.2 U24.3 | length 3.4
  Bottom Layer w0.254: R187.2@26.086,106.454 26.086,106.479 26.878,107.271 26.963,107.271 27.732,108.04 28.67,108.04 U24.3@28.765,108.135
NetR193_2: R193.2 U34.12 | length 8.9
  Bottom Layer w0.254: U34.12@282.225,59.435 282.75,59.435 282.923,59.262 282.923,59.037 284.071,57.888 287.203,57.888 288.531,59.216 288.531,59.396 289.275,60.14 R193.2@289.3,60.14
NetR194_2: R194.2 U35.12 | length 8.2
  Bottom Layer w0.254: U35.12@282.225,30.788 282.75,30.788 283.588,29.95 283.588,29.601 284.171,29.018 287.18,29.018 288.77,30.608 R194.2@288.795,30.608
NetR206_2: R206.2 U34.13 | length 7.8
  Bottom Layer w0.254: U34.13@282.225,58.165 282.75,58.165 283.484,57.431 288.173,57.431 289.275,58.533 R206.2@289.3,58.533
NetR207_2: R207.2 U35.13 | length 7
  Bottom Layer w0.254: U35.13@282.225,29.518 282.75,29.518 283.707,28.56 287.795,28.56 288.028,28.793 288.755,28.793 R207.2@288.76,28.788
NetR209_1: R209.1 U29.6 | length 11.9
  Bottom Layer w0.508: U29.6@38.866,94.24 38.912,94.194 39.437,94.194 40.148,93.483 40.148,93.024 40.723,92.448 47.549,92.448 48.312,93.212 48.587,93.212 48.983,93.608 R209.1@48.983,93.883
NetR210_2: R210.2 U37.12 | length 9
  Bottom Layer w0.254: R210.2@22.611,37.363 22.893,37.645 22.893,38.564 24.048,39.719 27.594,39.719 27.919,39.394 27.919,38.814 28.355,38.378 28.982,38.378 U37.12@29.155,38.205
NetR211_2: R211.2 U38.12 | length 11.4
  Bottom Layer w0.254: R211.2@22.693,63.853 22.82,63.98 22.82,64.409 23.104,64.693 23.104,65.096 23.11,65.102 23.11,67.56 24.354,68.804 27.208,68.804 27.813,68.199 27.813,67.564 28.1,67.277 U38.12@29.116,67.277
NetR212_2: R212.2 U37.13 | length 7.3
  Bottom Layer w0.254: R212.2@22.465,40 23.598,40 24.038,40.44 27.665,40.44 28.63,39.475 U37.13@29.155,39.475
NetR213_2: R213.2 U38.13 | length 10.1
  Bottom Layer w0.254: R213.2@22.195,65.532 22.195,67.487 24.156,69.448 27.373,69.448 28.132,68.689 28.973,68.689 U38.13@29.116,68.547
NetR215_1: R215.1 U30.6 | length 15.3
  Bottom Layer w0.508: U30.6@38.765,122.481 38.811,122.435 39.336,122.435 40.509,121.261 40.624,121.261 40.627,121.258 44.97,121.258 44.973,121.261 47.09,121.261 49.513,118.838 49.949,118.838 51.59,117.198 R215.1@51.59,116.923
NetR216_1: R216.1 U29.4 | length 10.2
  Bottom Layer w0.508: U29.4@38.866,96.78 40.541,96.78 40.712,96.61 44.99,96.61 ; 44.991,96.611 R216.1@48.983,96.611
NetR218_1: R218.1 U30.4 | length 16.4
  Bottom Layer w0.508: U30.4@38.765,125.021 38.811,124.975 39.336,124.975 39.478,124.832 46.907,124.832 47.204,124.535 47.204,122.282 49.937,119.55 51.56,119.55 R218.1@51.59,119.52
NetR219_2: R219.2 R221.1 | length 63.9
  Inner Layer1 w0.254: v1(50.193,104.857) 50.193,84.313 47.348,81.468 47.348,78.664 43.639,74.954 43.639,61.966 47.595,58.01 47.595,53.878 50.177,51.296 50.177,50.375 v1(50.214,50.338)
  Bottom Layer w0.254: v1(50.193,104.857) 51.094,104.857 51.617,105.38 R219.2@51.617,105.422 ; v1(50.214,50.338) 51.262,50.338 51.785,49.815 R221.1@51.785,49.377
NetR222_1: R222.1 R228.2 | length 2
  Top Layer w0.508: R222.1@248.244,21.345 R228.2@250.263,21.345
NetR224_2: R224.2 R225.1 | length 65.5
  Inner Layer1 w0.254: v1(50.193,108.695) 50.193,106.866 50.889,106.171 50.889,84.362 47.806,81.279 47.806,78.474 44.179,74.848 44.179,62.228 48.053,58.355 48.053,54.186 49.513,52.726 v1(50.297,52.726)
  Bottom Layer w0.254: v1(50.193,108.695) R224.2@51.516,108.695 ; v1(50.297,52.726) R225.1@51.747,52.726 ; R224.2@51.643,107.958 R224.2@51.643,108.658
NetR227_2: R227.2 R229.1 | length 65.1
  Inner Layer1 w0.254: v1(49.386,57.155) 49.339,57.202 49.339,57.716 44.637,62.418 44.637,74.659 48.263,78.285 48.263,81.089 51.346,84.172 51.346,111.128 v1(50.442,112.032)
  Bottom Layer w0.254: v1(49.386,57.155) 50.55,57.155 50.868,56.837 R229.1@50.868,56.137 R229.1@50.796,56.209 ; v1(50.442,112.032) 51.553,112.032 R227.2@51.617,112.097 ; R227.2@51.693,111.332 R227.2@51.617,111.408 ; R227.2@51.617,111.408 R227.2@51.617,112.097 ; R227.2@51.617,111.408 R227.2@51.617,112.097
NetR231_2: R231.2 R240.2 U31.1 U31.4 U31.10 U31.13 | length 35.4
  Bottom Layer w0.254: U31.1@17.964,10.677 17.964,10.985 17.873,11.075 16.662,11.075 16.333,11.405 13.335,11.405 12.807,11.933 12.807,12.45 11.762,13.495 R231.2@10.053,13.495 10.053,11.297 10.78,10.57 10.78,8.72 12.207,7.292 12.207,4.836 13.335,3.708 18.427,3.708 18.614,3.895 ; U31.1@17.964,11.025 17.964,12.426 18.48,12.943 19.467,12.943 19.914,12.497 U31.4@19.914,10.677 ; U31.13@18.614,4.777 18.614,3.895 ; U31.10@20.564,4.777 20.564,3.952 20.358,3.746 18.762,3.746 18.614,3.895
NetR241_1: R241.1 U27.32 | length 2.8
  Bottom Layer w0.254: R241.1@269.944,74.145 269.954,74.135 270.844,74.135 271.279,73.7 272.43,73.7 U27.32@272.525,73.605
NetR243_2: R243.2 U27.3 | length 3.3
  Bottom Layer w0.254: U27.3@282.475,74.905 282.57,75 283.592,75 285.099,76.507 R243.2@285.099,76.532
NetR245_2: R245.2 U28.3 | length 3.2
  Bottom Layer w0.254: U28.3@282.475,46.42 283.693,46.42 284.732,47.46 284.757,47.46 285.105,47.808 R245.2@285.105,47.833
NetR251_2: R251.2 U40.12 | length 8.3
  Bottom Layer w0.254: U40.12@282.225,115.371 283.282,115.371 283.431,115.223 283.431,114.424 283.799,114.056 288.015,114.056 288.698,114.739 288.698,114.764 289.046,115.112 R251.2@289.071,115.112
NetR252_2: R252.2 U41.12 | length 8.6
  Bottom Layer w0.254: U41.12@282.205,87.311 283.31,87.311 283.458,87.163 283.458,86.182 283.779,85.861 287.407,85.861 288.95,87.404 R252.2@288.975,87.404
NetR263_2: R263.2 U40.13 | length 7.2
  Bottom Layer w0.254: U40.13@282.225,114.101 282.75,114.101 283.252,113.599 288.854,113.599 R263.2@288.879,113.624 ; R263.2@288.831,113.672 R263.2@289.071,113.432
NetR264_2: R264.2 U41.13 | length 7.1
  Bottom Layer w0.254: U41.13@282.205,86.041 282.73,86.041 283.367,85.404 287.715,85.404 287.887,85.576 R264.2@288.961,85.576
NetR272_1: R272.1 U34.6 | length 13
  Bottom Layer w0.508: R272.1@261.149,59.486 261.467,59.804 262.263,59.804 264.513,62.054 270.627,62.054 271.904,60.777 271.904,60.751 271.95,60.705 U34.6@272.475,60.705
NetR274_1: R274.1 U35.6 | length 14
  Bottom Layer w0.508: R274.1@261.105,36.68 261.105,36.405 261.501,36.009 261.776,36.009 262.794,34.991 265.172,34.991 265.762,34.4 265.762,34.226 266.353,33.636 270.895,33.636 271.193,33.338 271.193,32.591 271.681,32.103 272.429,32.103 U35.6@272.475,32.058
NetR275_1: R275.1 U34.4 | length 12
  Bottom Layer w0.508: R275.1@261.149,56.98 261.149,57.255 261.545,57.651 262.883,57.651 263.397,58.165 U34.4@272.475,58.165
NetR277_1: R277.1 U35.4 | length 13.9
  Bottom Layer w0.508: R277.1@261.105,34.191 263.246,34.191 264.068,33.369 264.075,33.369 265.88,31.564 265.88,30.522 266.885,29.518 U35.4@272.475,29.518
NetR281_1: R281.1 R327.2 | length 3
  Top Layer w1.27: R281.1@65.265,21.697 65.265,21.972 65.895,22.602 65.895,24.465 R327.2@65.91,24.48
NetR285_1: R285.1 R359.2 | length 2
  Top Layer w0.508: R285.1@258.105,21.345 R359.2@260.068,21.345
NetR286_2: R286.2 U32.3 | length 6
  Bottom Layer w0.254: R286.2@27.331,47.219 27.331,51.547 27.599,51.815 U32.3@28.905,51.815
NetR288_1: R288.1 U33.32 | length 2.7
  Bottom Layer w0.254: U33.32@38.855,24.075 38.883,24.047 39.979,24.047 40.493,23.533 R288.1@41.307,23.533
NetR291_2: R291.2 U33.3 | length 5.1
  Bottom Layer w0.254: R291.2@27.28,17.932 27.28,22.14 27.915,22.775
NetR316_1: R316.1 U37.6 | length 18.5
  Bottom Layer w0.508: U37.6@38.905,36.935 39.43,36.935 40.78,35.585 40.794,35.585 40.795,35.583 46.456,35.583 47.209,36.337 47.209,38.792 50.603,42.186 51.868,42.186 52.264,41.79 R316.1@52.264,41.515
NetR318_1: R318.1 U38.6 | length 13.6
  Bottom Layer w0.508: U38.6@38.866,66.007 38.912,65.961 39.437,65.961 40.155,65.242 40.155,64.987 40.678,64.464 47.453,64.464 48.828,65.84 R318.1@51.134,65.84
NetR319_1: R319.1 U37.4 | length 15.4
  Bottom Layer w0.508: U37.4@38.905,39.475 46.872,39.475 50.757,43.36 51.849,43.36 52.245,43.756 R319.1@52.245,44.031
NetR321_1: R321.1 U38.4 | length 12.4
  Bottom Layer w0.508: U38.4@38.866,68.547 50.882,68.547 R321.1@51.134,68.295
NetR327_1: R327.1 R361.2 | length 2.5
  Top Layer w1.27: R327.1@68.81,24.48 68.81,24.5 68.825,24.515 71.235,24.515 R361.2@71.25,24.53
NetR328_1: R328.1 U39.32 | length 2.7
  Bottom Layer w0.254: R328.1@270.022,130.072 270.903,130.072 271.35,129.625 272.43,129.625 U39.32@272.525,129.53
NetR329_2: R329.2 U39.3 | length 3.3
  Bottom Layer w0.254: U39.3@282.475,130.83 282.57,130.925 283.508,130.925 284.234,131.651 284.236,131.651 285.07,132.484 R329.2@285.07,132.509
NetR338_2: R338.2 R339.1 R340.1 | length 98.3
  Top Layer w0.254: v1(255.803,123.495) 255.803,130.862 255.987,131.045 R339.1@256.592,131.045
  Inner Layer1 w0.254: v1(255.803,123.495) 255.803,122.801 259.94,118.665 259.94,113.059 260.569,112.43 260.569,110.688 260.357,110.475 260.357,104.387 261.047,103.697 261.047,100.78 v1(260.467,100.2) 258.87,98.603 258.87,85.637 256.009,82.776 256.009,72.244 260.147,68.106 260.147,59.92 259.539,59.312 259.539,51.126 258.888,50.474 258.888,47.262 260.433,45.716 v1(262.46,45.716)
  Bottom Layer w0.254: R338.2@259.05,100.004 259.245,100.2 v1(260.467,100.2) ; v1(262.46,45.716) R340.1@262.46,47.166
NetR341_2: R341.2 R342.1 R343.1 | length 91.3
  Top Layer w0.254: R342.1@253.372,131.045 254.072,131.045 254.595,130.522 254.595,123.449 254.66,123.384 v1(254.66,123.317)
  Inner Layer1 w0.254: v1(254.66,123.317) 254.66,123.298 259.483,118.475 259.483,112.754 260.112,112.125 260.112,110.877 259.9,110.665 259.9,103.849 v1(260.467,103.282) 260.467,101.557 258.375,99.465 258.375,85.79 255.552,82.967 255.552,72.048 259.69,67.911 259.69,60.165 259.082,59.557 259.082,51.855 v1(257.853,50.626)
  Bottom Layer w0.254: v1(257.853,50.626) 257.853,51.846 R343.1@258.005,51.999 ; R341.2@259.05,103.304 259.05,103.282 v1(260.467,103.282)
NetR344_2: R344.2 U36.3 | length 3.2
  Bottom Layer w0.254: U36.3@282.426,102.938 282.521,103.033 283.71,103.033 284.662,103.984 284.685,103.984 285.033,104.332 R344.2@285.033,104.357
NetR359_1: R359.1 R363.2 | length 1.9
  Top Layer w0.508: R359.1@262.968,21.345 R363.2@264.877,21.345
NetR368_1: R368.1 U40.6 | length 15.6
  Bottom Layer w0.508: R368.1@261.653,111.547 261.653,111.822 262.049,112.218 262.572,112.218 264.486,114.133 264.486,117.048 265.035,117.597 270.79,117.597 271.7,116.687 272.429,116.687 U40.6@272.475,116.641
NetR370_1: R370.1 U41.6 | length 13.9
  Bottom Layer w0.508: R370.1@261.147,87.601 261.147,87.515 261.543,87.119 262.961,87.119 266.19,90.348 270.697,90.348 270.971,90.075 270.971,89.541 271.93,88.581 U41.6@272.455,88.581
NetR371_1: R371.1 U40.4 | length 13.8
  Bottom Layer w0.508: R371.1@261.65,108.92 261.65,109.195 263.144,110.689 263.144,111.785 265.46,114.101 U40.4@272.475,114.101
NetR373_1: R373.1 U41.4 | length 12.1
  Bottom Layer w0.508: R373.1@261.165,85.202 261.165,85.477 261.561,85.873 261.764,85.873 262.286,86.395 270.516,86.395 270.869,86.041 U41.4@272.455,86.041
NetR379_2: R379.2 R380.1 R381.1 | length 95.8
  Top Layer w0.254: v1(256.642,122.936) 256.642,128.088 259.598,131.045 R380.1@260.298,131.045
  Inner Layer1 w0.254: v1(256.642,122.936) 260.477,119.101 260.477,113.284 261.112,112.649 261.112,110.584 260.814,110.286 260.814,104.692 261.504,104.002 261.504,100.095 259.619,98.21 259.619,91.467 260.038,91.049 260.038,90.936 259.619,90.518 259.619,85.653 256.467,82.5 256.467,72.47 260.604,68.333 260.604,59.73 259.996,59.123 259.996,50.765 v1(261.892,48.87)
  Bottom Layer w0.254: v1(260.038,90.993) 261.036,90.993 261.559,91.516 R379.2@261.559,92.125 ; R381.1@260.63,49.8 260.63,49.393 261.153,48.87 v1(261.892,48.87)
OVP_EFUSE: R71.1 R75.2 U4.5 | length 3.9
  Bottom Layer w0.254: U4.5@8.932,122.387 9.027,122.482 9.027,124.176 R71.1@9.357,124.507 9.357,126.009 R75.2@9.43,126.082
PGND: C16.2 C20.2 C23.1 C24.1 C26.2 C30.2 C59.2 C60.2 C139.2 C273.1 MP6.1 MP6.2 MP10.1 MP10.2 Q12.2 Q13.2 R36.1 R58.2 R158.1 R361.1 U21.3 U21.4 | length 103.6
  Top Layer w1.27: MP6.2@52.584,78.839 52.584,74.386 MP10.1@52.69,74.28
  Inner Layer1 w1.27: MP6.2@52.584,78.839 52.584,74.386 MP10.1@52.69,74.28
  Inner Layer2 w1.27: MP6.2@52.584,78.839 52.584,74.386 MP10.1@52.69,74.28
  Bottom Layer w0.508: C60.2@60,140 65.241,140 C23.1@72.221,133.02 ; U21.4@60.853,145.012 61.453,145.012 62.116,144.348 C273.1@64.858,144.348 64.838,144.368 64.838,146.007 R158.1@64.818,146.027 ; U21.3@60.853,146.282 61.453,146.282 61.708,146.027 C139.2@63.1,146.027 R158.1@64.818,146.027 ; v1@73.429,147.491 v1(73.448,147.51) ; v1(73.448,146.2) 73.275,146.027 R158.1@64.818,146.027
  Bottom Layer w1.27: MP10.2@52.576,28.28 56.218,24.638 66.802,24.638 70.954,28.79 v1(70.954,28.82) ; MP6.2@52.584,78.839 52.584,74.386 MP10.1@52.69,74.28 ; C24.1@115.43,133.02 134.061,133.02 134.92,133.879 C59.2@134.92,143.68
  other v1: 72.001,28.811 68.96,28.826 69.911,28.865 69.911,29.747 70.956,29.747 72.001,29.747 69.911,30.682 70.956,30.682 72.001,30.682 70.956,31.618 72.001,31.618 64.106,61.966 65.152,61.966 66.197,61.966 67.242,61.966 64.106,62.901 65.152,62.901 66.197,62.901 67.242,62.901 64.106,63.837 65.152,63.837 66.197,63.837 67.242,63.837 64.165,64.772 65.191,64.772 66.216,64.772 67.242,64.772 64.048,74.484 65.093,74.484 66.138,74.484 67.183,74.484 64.048,75.42 65.093,75.42 66.138,75.42 67.183,75.42 64.048,76.355 65.093,76.355 66.138,76.355 67.183,76.355 64.106,77.291 65.132,77.291 66.157,77.291 67.183,77.291 63.588,112.2 64.633,112.2 65.678,112.2 66.723,112.2 63.588,113.136 64.633,113.136 65.678,113.136 66.723,113.136 63.588,114.072 64.633,114.072 65.678,114.072 66.723,114.072 63.588,115.007 64.633,115.007 65.678,115.007 66.723,115.007 63.647,115.943 64.672,115.943 65.698,115.943 66.723,115.943 64.592,121.488 65.637,121.488 66.682,121.488 64.651,122.424 65.677,122.424 66.702,122.424 74.448,146.2 75.548,146.2 76.568,146.2 77.58,146.2 78.58,146.2 79.68,146.2 80.7,146.2 74.448,147.51 75.548,147.51 76.568,147.51 77.58,147.51 78.58,147.51 79.68,147.51 80.7,147.51 73.448,148.82 74.448,148.82 75.548,148.82 76.568,148.82 77.58,148.82 78.58,148.82 79.68,148.82 80.7,148.82
Prof_GPIO1: J2.62 J4.2 | length 7.2
  Top Layer w0.254: J2.62@10.069,50.979 12.762,50.979 14.335,52.552 J4.2@16.662,52.552
Prof_GPIO2: J2.64 J4.1 | length 4.5
  Top Layer w0.254: J2.64@10.069,50.179 10.192,50.056 12.276,50.056 12.954,49.378 13.948,49.378 J4.1@14.122,49.552
PWM1A: J2.49 R182.2 U26.2 | length 15.4
  Top Layer w0.254: v1@4.116,58.972 v1@4.232,58.972 ; v1@4.225,58.965 v1@4.232,58.972 ; J2.49@6.669,58.979 6.662,58.972 v1@4.232,58.972
  Bottom Layer w0.254: v1(4.109,58.965) 4.109,60.587 6.017,62.495 R182.2@7.686,62.495 7.711,62.495 8.67,61.536 12.168,61.536 13.106,62.473 13.106,63.083 U26.2@13.143,63.121
PWM1A_1: PWM1.1 R177.2 R200.1 R203.1 U26.3 | length 79.8
  Top Layer w0.254: v1(13.793,61.837) 17.641,61.837 22.239,66.435 22.239,90.718 v1(23.786,92.264) ; v1(23.8,122.615) 23.8,119.965 24.147,119.618 24.147,118.889 23.505,118.247 23.505,114.781 23.643,114.642 23.643,114.161 23.505,114.023 23.505,100.828 24.997,99.336 24.997,94.085 23.797,92.885 23.797,92.275 v1(23.786,92.264) ; PWM1.1@26.618,93.304 26.618,93.026 25.856,92.264 v1(23.786,92.264)
  Bottom Layer w0.254: v1(13.793,61.837) U26.3@13.793,63.121 ; R177.2@22.585,88.981 22.61,88.981 22.958,89.329 22.958,89.354 23.786,90.182 v1(23.786,92.264) 24.969,92.264 R200.1@25.056,92.351 ; v1(23.8,122.615) 24.926,122.615 R203.1@24.944,122.597
PWM1B: J2.51 R181.2 U26.5 | length 17.9
  Top Layer w0.254: v1(4.109,58.179) J2.51@6.669,58.179
  Bottom Layer w0.254: v1(4.109,58.179) 4.144,58.179 5.41,59.445 5.41,60.762 5.751,60.762 6.698,59.814 13.064,59.814 15.056,61.806 15.056,63.083 U26.5@15.093,63.121
PWM1B_1: PWM2.1 R176.2 R201.1 R202.1 U26.6 | length 76.3
  Top Layer w0.254: v1(17.848,64.03) 18.31,64.03 20.283,66.003 20.283,90.408 v1(23.905,94.029) 22.225,95.709 22.225,120.367 22.764,120.906 22.764,122.586 23.455,123.277 25.614,123.277 PWM2.1@26.294,122.597 ; PWM2.1@26.039,122.352 PWM2.1@26.284,122.597
  Bottom Layer w0.254: U26.6@15.743,63.121 15.781,63.158 15.781,63.769 16.163,64.151 17.661,64.151 17.782,64.03 v1(17.848,64.03) ; v1(22.764,120.989) R201.1@24.944,120.989 ; v1@22.863,120.793 22.863,117.987 R176.2@23.211,117.639 ; v1(23.905,94.029) R202.1@25.056,94.029
PWM2A: J2.53 R180.2 U26.9 | length 18.1
  Top Layer w0.254: v1@4.082,57.383 v1@4.232,57.383 ; v1@4.228,57.387 v1@4.232,57.383 ; J2.53@6.669,57.379 6.664,57.383 v1@4.232,57.383
  Bottom Layer w0.254: v1(4.109,57.387) 4.789,57.387 5.679,58.277 R180.2@5.704,58.277 5.729,58.277 6.077,58.625 6.077,59.04 6.393,59.357 13.253,59.357 14.147,60.251 14.761,60.251 15.743,59.269 U26.9@15.743,57.221
PWM2A_1: PWM3.1 R175.2 R303.1 R306.1 U26.8 | length 55.6
  Top Layer w0.254: v1(16.44,60.415) 17.743,60.415 23.374,66.046 v1(23.905,66.046) 25.897,64.053 25.897,62.175 24.309,60.587 24.309,56.89 23.47,56.051 23.47,46.151 24.395,45.226 24.395,44.746 23.966,44.317 23.966,44.106 24.618,43.454 24.618,36.937 23.915,36.234 23.915,35.69 v1(23.905,35.679) 25.426,35.679 25.945,36.197 PWM3.1@25.945,36.822
  Bottom Layer w0.254: U26.8@16.393,57.221 16.416,57.244 16.416,60.391 v1(16.44,60.415) ; R175.2@22.688,32.266 22.688,34.462 v1(23.905,35.679) R303.1@25.145,35.679 ; v1(23.905,66.046) 25.057,66.046 R306.1@25.097,66.006
PWM2B: J2.55 R179.2 U26.12 | length 14.2
  Top Layer w0.254: v1(4.116,56.573) 4.12,56.577 6.667,56.577 J2.55@6.669,56.579
  Bottom Layer w0.254: v1(4.116,56.573) 4.183,56.573 4.305,56.451 R179.2@5.716,56.453 R179.2@5.716,56.453 ; R179.2@5.74,56.452 6.546,57.259 9.415,57.259 10.865,58.708 12.916,58.708 13.756,57.869 13.756,57.258 U26.12@13.793,57.221
PWM2B_1: PWM4.1 R174.2 R304.1 R305.1 U26.11 | length 49.3
  Top Layer w0.254: v1(14.443,59.671) 18.65,59.671 23.419,64.44 v1(23.905,64.44) 24.622,63.722 24.622,62.341 23.089,60.808 PWM4.1@23.089,58.742 22.428,58.08 22.428,45.616 22.807,45.237 22.807,38.739 22.731,38.663 22.731,38.452 v1(23.905,37.279)
  Bottom Layer w0.254: U26.11@14.443,57.221 v1(14.443,59.671) ; R174.2@22.731,61.028 22.731,62.412 23.204,62.884 23.905,63.585 v1(23.905,64.44) 25.063,64.44 R304.1@25.097,64.406 ; v1(23.905,37.279) 25.126,37.279 R305.1@25.145,37.297
PWM3A: J2.50 R239.2 U31.2 | length 62.2
  Top Layer w0.254: J2.50@10.069,58.979 16.315,58.979 21.307,53.987 21.307,14.791 v1(18.614,12.098)
  Bottom Layer w0.254: R239.2@15.475,10.24 16.405,10.24 17.17,9.474 18.237,9.474 18.614,9.851 v1(18.614,12.098)
PWM3A_1: PWM5.1 R235.2 R259.1 R262.1 U31.3 | length 329.4
  Top Layer w0.254: v1(24.928,8.392) 24.975,8.345 25.149,8.345 25.192,8.302 277.567,8.302 289.336,20.071 289.336,29.561 287.479,31.418 v1(287.479,31.979) 288.393,32.893 288.798,32.893 289.974,34.069 289.974,59.496 v1(287.252,62.218)
  Top Layer w0.508: PWM5.1@285.285,61.035 285.285,61.583 285.92,62.218 v1(287.252,62.218)
  Bottom Layer w0.254: U31.3@19.264,10.677 19.264,9.075 20.21,8.128 24.656,8.128 24.92,8.392 v1(24.928,8.392) ; R259.1@286.09,62.165 286.143,62.218 v1(287.252,62.218) 288.864,62.218 R235.2@288.885,62.196 ; R262.1@286.125,31.979 v1(287.479,31.979)
PWM3B: J2.52 R238.2 U31.5 | length 60.8
  Top Layer w0.254: J2.52@10.069,58.179 15.735,58.179 20.117,53.797 20.117,47.955 19.741,47.579 19.741,47.099 19.863,46.977 19.863,15.142 v1(19.197,14.477)
  Bottom Layer w0.254: R238.2@15.843,12.482 15.843,13.49 16.83,14.477 v1(19.197,14.477) 20.564,13.11 U31.5@20.564,10.677
PWM3B_1: PWM6.1 R234.2 R260.1 R261.1 U31.6 | length 319.5
  Top Layer w0.254: v1(24.928,9.484) 24.941,9.497 276.994,9.497 288.036,20.539 288.036,23.643 286.852,24.827 286.852,32.925 v1(287.497,33.57) 289.06,35.133 289.06,51.396 288.095,52.362 288.095,59.712 v1(287.252,60.555)
  Bottom Layer w0.254: U31.6@21.214,10.677 21.214,11.562 21.565,11.913 22.5,11.913 v1(24.928,9.484) ; R261.1@286.09,60.555 v1(287.252,60.555) v1@287.366,60.555 ; R260.1@286.125,33.58 286.135,33.57 v1(287.497,33.57) 288.75,33.57 R234.2@288.76,33.58
PWM4A: J2.54 R237.2 U31.9 | length 65.3
  Top Layer w0.254: J2.54@10.069,57.379 15.429,57.379 18.372,54.436 18.372,47.945 18.509,47.808 18.509,44.926 18.72,44.715 18.72,14.91 17.653,13.843 17.653,10.391 19.719,8.326 19.719,8.081 v1(21.251,6.549)
  Bottom Layer w0.254: U31.9@21.214,4.777 21.229,4.761 21.229,3.968 21.59,3.607 23.335,3.607 23.675,3.946 23.675,3.971 24.023,4.319 R237.2@24.048,4.319 ; U31.9@21.232,4.795 21.232,6.53 v1(21.251,6.549)
PWM4A_1: PWM7.1 R233.2 R352.1 R355.1 U31.8 | length 387.4
  Top Layer w0.254: v1(24.955,5.932) 24.976,5.911 151.848,5.911 151.918,5.841 278.724,5.841 292.291,19.409 292.291,61.574 290.869,62.996 290.869,84.162 287.232,87.799 v1(287.232,88.431) 290.22,91.42 290.22,115.186 v1(287.252,118.154) 285.618,118.154 PWM7.1@284.867,117.404
  Bottom Layer w0.254: U31.8@21.864,4.777 21.864,5.658 22.137,5.932 v1(24.955,5.932) ; R355.1@285.889,88.382 285.938,88.431 v1(287.232,88.431) ; R352.1@286.036,118.129 286.061,118.154 v1(287.252,118.154) 288.951,118.154 R233.2@288.961,118.144
PWM4B: J2.56 R236.2 U31.12 | length 64.4
  Top Layer w0.254: J2.56@10.069,56.579 15.1,56.579 17.501,54.178 17.501,49.456 17.063,49.019 17.063,34.146 17.729,33.48 17.729,15.545 16.377,14.193 16.377,10.157 v1(19.264,7.271)
  Bottom Layer w0.254: R236.2@15.475,8.604 17.93,8.604 v1(19.264,7.271) U31.12@19.264,4.777
PWM4B_1: PWM8.1 R232.2 R353.1 R354.1 U31.11 | length 385.3
  Top Layer w0.254: v1(24.941,7.215) 25.008,7.215 25.134,7.089 277.933,7.089 290.793,19.949 290.793,60.751 289.685,61.859 289.685,82.623 285.639,86.669 PWM8.1@285.639,88.501 ; PWM8.1@285.144,87.907 285.144,88.732 285.906,89.494 285.963,89.494 286.563,90.094 v1(287.232,90.094) 289.306,92.168 289.306,106.855 286.502,109.659 286.502,115.741 v1(287.252,116.491)
  Bottom Layer w0.254: U31.11@19.914,4.777 19.914,6.444 20.65,7.181 24.906,7.181 v1(24.941,7.215) ; R353.1@285.889,89.999 285.983,90.094 v1(287.232,90.094) 288.595,90.094 R232.2@288.689,89.999 ; R354.1@286.016,116.469 286.037,116.491 v1(287.252,116.491)
PWM_EN: J2.58 R173.1 R231.1 | length 49.1
  Top Layer w0.254: v1(8.048,46.799) 8.074,46.825 8.407,46.825 8.681,47.1 8.681,48.355 8.681,48.803 8.681,51.555 8.69,51.564 v1(8.69,52.579) J2.58@10.069,52.579
  Bottom Layer w0.254: R173.1@5.763,53.22 5.788,53.22 6.709,52.299 8.41,52.299 v1(8.69,52.579) ; v1(8.048,46.799) 8.095,46.752 8.095,46.24 8.78,45.555 8.78,36.86 14.011,31.629 14.011,27.414 8.453,21.856 R231.1@8.453,13.495
RDY: C322.1 J2.69 R79.2 R85.1 R144.1 R193.1 R194.1 R210.1 R211.1 R251.1 R252.1 | length 511.4
  Top Layer w0.254: J2.69@6.669,47.779 6.675,47.773 7.655,47.773 v1(7.661,47.766) ; v1(22.158,45.066) 22.192,45.031 22.192,39.013 v1(22.227,38.979)
  Inner Layer1 w0.254: v1(75.539,8.917) v1(83.949,8.917)
  Inner Layer2 w0.254: v1(17.714,34.316) 20.449,34.316 20.646,34.12 v1(20.712,34.12)
  Bottom Layer w0.254: R79.2@6.369,46.633 6.394,46.633 v1@7.479,47.719 ; v1(7.661,47.766) 7.708,47.719 8.745,47.719 9.265,47.199 C322.1@10.383,46.081 ; C322.1@10.383,46.056 10.035,45.708 10.035,44.913 9.737,44.615 9.737,37.295 13.406,33.626 17.024,33.626 v1(17.714,34.316) ; v1(20.712,34.12) 20.759,34.167 21.334,34.167 21.483,34.316 ; R211.1@21.131,63.853 21.275,63.998 21.275,66.491 21.09,66.677 21.09,66.754 21.022,66.822 21.022,67.303 21.236,67.517 21.236,90.7 21.017,90.918 21.017,95.113 20.55,95.58 20.55,105.162 21.48,106.092 R144.1@21.48,117.46 ; R211.1@21.169,63.853 21.042,63.726 21.042,48.086 21.359,47.769 21.359,46.909 21.184,46.734 21.184,46.04 v1(22.158,45.066) ; v1(22.227,38.979) 21.307,38.059 21.307,36.373 21.594,36.086 21.858,36.086 ; R210.1@22.611,35.763 22.288,36.086 21.858,36.086 ; v1(75.539,8.917) 33.404,8.917 23.808,18.512 22.927,18.512 21.483,19.957 21.483,34.316 ; v1(83.949,8.917) 85.288,8.917 86.565,7.64 278.484,7.64 292.291,21.448 292.291,30.385 292.069,30.608 ; R194.1@290.395,30.608 292.069,30.608 ; R252.1@290.575,87.404 292.252,87.404 ; R251.1@290.671,115.112 291.542,115.112 292.252,114.402 292.252,87.404 ; R193.1@290.9,60.14 291.08,59.96 292.293,59.96 292.336,59.917 ; 21.483,34.316 21.858,34.316 21.858,36.086 ; 292.069,30.608 292.291,30.83 292.291,59.872 292.336,59.917 ; 292.252,87.404 292.336,87.321 292.336,59.917
RELAY_N: D4.1 K3.1 Q3.1 Q3.2 Q3.5 Q3.6 Q3.8 | length 22.3
  Bottom Layer w0.508: K3.1@208.84,171.62 208.84,171.5 209.1,171.24 219.309,171.24 Q3.1@222.299,174.23 ; Q3.1@222.299,174.26 222.954,174.26 223.249,174.555 Q3.8@223.274,174.555 ; Q3.8@223.299,174.555 223.534,174.32 224.389,174.32 228.68,174.32 D4.1@229.24,174.88
RELAY_P: D2.1 K1.1 Q4.1 Q4.2 Q4.5 Q4.6 Q4.8 | length 20.6
  Bottom Layer w0.508: K1.1@155.52,171.62 155.52,172.3 156.784,173.564 156.784,173.824 157.221,174.261 157.221,174.361 Q4.8@166.51,174.361 173.574,174.361 D2.1@174.118,174.904
RTN: C66.2 R73.2 R74.1 R75.1 R77.1 U4.8 U4.17 | length 5.6
  Bottom Layer w0.254: R74.1@12.331,114.872 12.331,115.849 v1(12.856,116.375) ; R73.2@12.333,113.24 12.349,113.256 v1(13.598,113.256) ; C66.2@12.335,111.647 12.45,111.533 v1(13.701,111.533)
  Bottom Layer w0.508: R75.1@11.03,126.082 v1(12.255,126.082)
  other v2: 6.807,118.287 8.007,118.287 9.207,118.287 10.407,118.287 6.807,119.487 8.007,119.487 9.207,119.487 10.407,119.487 6.807,120.687 8.007,120.687 9.207,120.687 10.407,120.687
